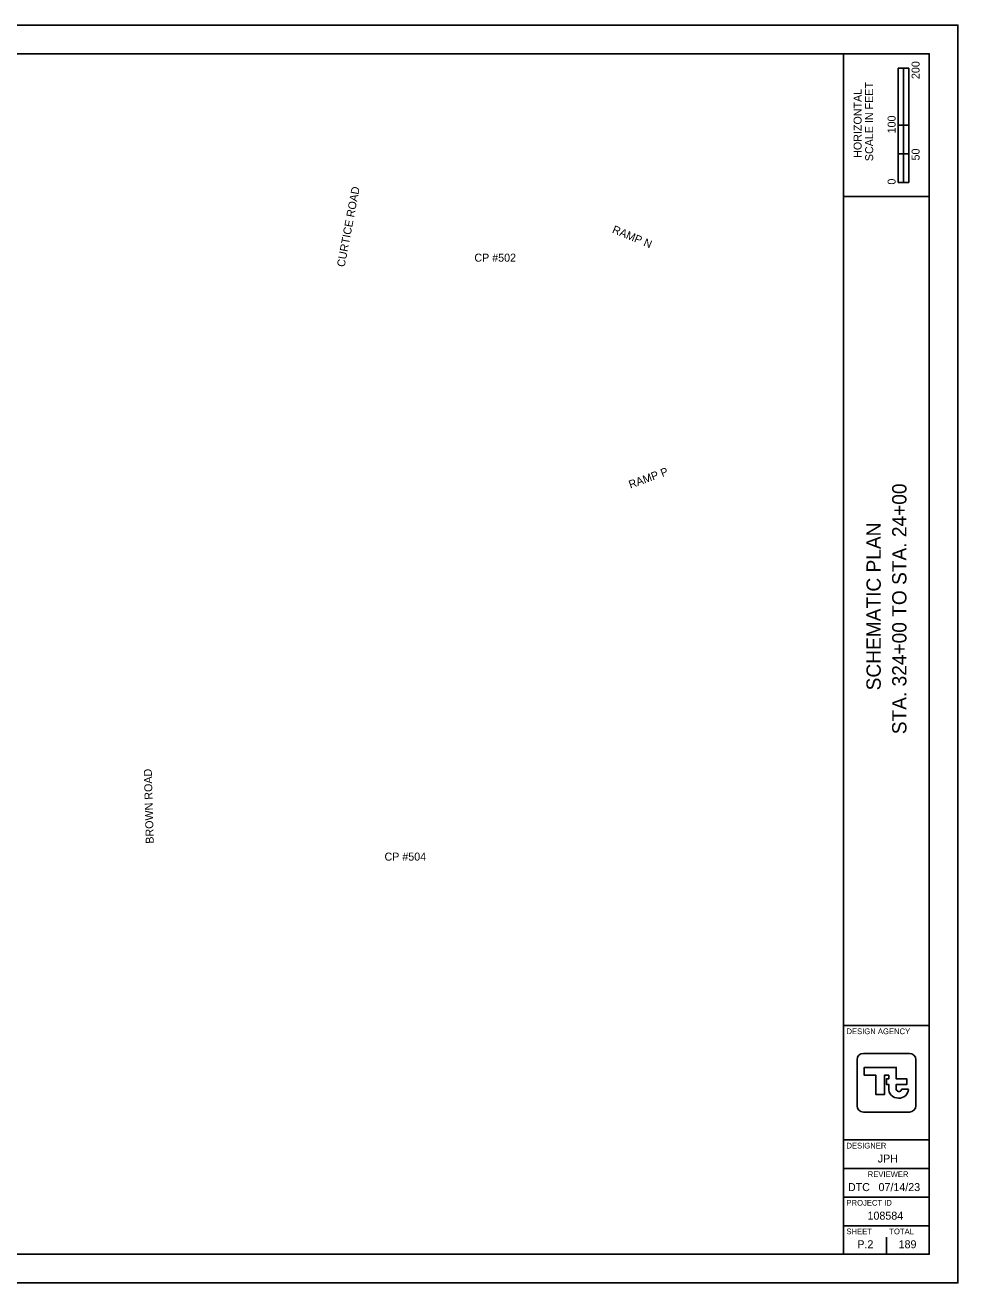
# Model space of a CAD drawing. Extents: x -1.8 to 34, y 0 to 22.
# Drawn here: x 17.67 to 34, y 0 to 22 of the extents above; entities that cross this region are included whole.
import ezdxf

# ---------------------------------------------------------------- set-up
doc = ezdxf.new("R2010")
doc.units = 0
for name, color, linetype in [('SH_Border', 7, 'Continuous'), ('SH_Cut_Line', 7, 'Continuous'), ('SH_Data', 7, 'Continuous'), ('SH_Text', 7, 'Continuous')]:
    doc.layers.add(name, color=color, linetype=linetype)

msp = doc.modelspace()

# ---------------------------------------------------------------- linework, layer by layer
at = {"layer": 'SH_Border'}
for p, q in [((32, 0.5), (32, 21.5)), ((32, 19), (33.5, 19)), ((32, 4.5), (33.5, 4.5)), ((32, 2.5), (33.5, 2.5)), ((32, 2), (33.5, 2)), ((32, 1.5), (33.5, 1.5)), ((32, 1), (33.5, 1))]:
    msp.add_line(p, q, dxfattribs=at)
msp.add_lwpolyline([(1.5, 21.5), (33.5, 21.5), (33.5, 0.5), (1.5, 0.5)], close=True, dxfattribs=at)
at = {"layer": 'SH_Cut_Line'}
msp.add_lwpolyline([(0, 0), (34, 0), (34, 22), (0, 22)], close=True, dxfattribs=at)
at = {"layer": 'SH_Data'}
for p, q in [((32.957, 19.25), (32.957, 21.25)), ((33.144, 21.25), (32.957, 21.25)), ((32.957, 20.25), (32.957, 21.25)), ((32.957, 21.25), (33.05, 21.25)), ((33.05, 21.25), (33.051, 21.25)), ((33.051, 21.25), (33.051, 20.25)), ((33.144, 21.25), (33.144, 19.25)), ((33.051, 20.25), (32.957, 20.25)), ((33.143, 20.25), (33.05, 20.25)), ((33.05, 20.25), (33.05, 19.75)), ((33.143, 19.75), (33.143, 20.25)), ((33.05, 19.75), (32.957, 19.75)), ((32.957, 19.75), (32.957, 19.25)), ((33.05, 19.25), (33.05, 19.75)), ((33.05, 19.75), (33.143, 19.75)), ((33.144, 19.25), (32.957, 19.25)), ((32.957, 19.25), (33.05, 19.25)), ((32.75, 3.5), (32.75, 3.5)), ((32.791, 3.415), (32.791, 3.415)), ((33.136, 3.385), (33.015, 3.385)), ((32.375, 0.675), (32.375, 0.675)), ((32.75, 0.5), (32.75, 0.8))]:
    msp.add_line(p, q, dxfattribs=at)
for points in [[(32.348, 4.014), (33.152, 4.014)], [(32.236, 3.099), (32.236, 3.901)], [(32.922, 3.399), (32.922, 3.47), (33.107, 3.47), (33.107, 3.568), (32.922, 3.568), (32.922, 3.768), (32.361, 3.768), (32.361, 3.632), (32.566, 3.632), (32.566, 3.294), (32.715, 3.294), (32.715, 3.63), (32.79, 3.63), (32.79, 3.568), (32.748, 3.568), (32.748, 3.47), (32.79, 3.47), (32.79, 3.415), (32.791, 3.415)], [(33.264, 3.901), (33.264, 3.099)], [(33.152, 2.986), (32.348, 2.986)]]:
    msp.add_lwpolyline(points, dxfattribs=at)
for centre, radius, start, end in [((32.348, 3.901), 0.113, 90, 180), ((33.152, 3.901), 0.113, 360, 90), ((32.949, 3.392), 0.16, 171.8856, 274.8323), ((32.968, 3.392), 0.0473, 171.8856, 350.9243), ((32.976, 3.392), 0.16, 265.1677, 357.3201), ((32.348, 3.099), 0.113, 180, 270), ((33.152, 3.099), 0.113, 270, 360)]:
    msp.add_arc(centre, radius, start, end, dxfattribs=at)

# ---------------------------------------------------------------- texts
for s, height, p in [('200', 0.14, (33.33, 21.057)), ('SCALE IN FEET', 0.14, (32.517, 19.621)), ('HORIZONTAL', 0.14, (32.315, 19.679)), ('100', 0.14, (32.91, 20.107)), ('50', 0.14, (33.33, 19.633)), ('0', 0.14, (32.91, 19.211)), ('STA. 324+00 TO STA. 24+00', 0.25, (33.1, 9.597)), ('SCHEMATIC PLAN', 0.25, (32.65, 10.364))]:
    msp.add_text(s, height=height, rotation=90, dxfattribs=at).set_placement(p)
for s, height, p in [('DESIGN AGENCY', 0.1, (32.05, 4.35)), ('DESIGNER', 0.1, (32.05, 2.35)), ('JPH', 0.14, (32.598, 2.105)), ('REVIEWER', 0.1, (32.422, 1.85)), ('DTC', 0.14, (32.076, 1.605)), ('07/14/23', 0.14, (32.611, 1.605)), ('PROJECT ID', 0.1, (32.05, 1.35)), ('108584', 0.14, (32.418, 1.105)), ('SHEET', 0.1, (32.05, 0.85)), ('TOTAL', 0.1, (32.8, 0.85)), ('P.2', 0.14, (32.24, 0.605)), ('189', 0.14, (32.963, 0.605))]:
    msp.add_text(s, height=height, dxfattribs=at).set_placement(p)
at = {"layer": 'SH_Text'}
for s, rotation, p in [('CURTICE ROAD', 79.2357, (23.264, 17.762)), ('RAMP N', 337.418, (27.937, 18.374)), ('RAMP P', 20.0072, (28.268, 13.892)), ('BROWN ROAD', 91.5727, (19.924, 7.684))]:
    msp.add_text(s, height=0.14, rotation=rotation, dxfattribs=at).set_placement(p)
for s, p in [('CP #502', (25.536, 17.863)), ('CP #504', (23.963, 7.386))]:
    msp.add_text(s, height=0.14, dxfattribs=at).set_placement(p)

doc.saveas('drawing.dxf')
